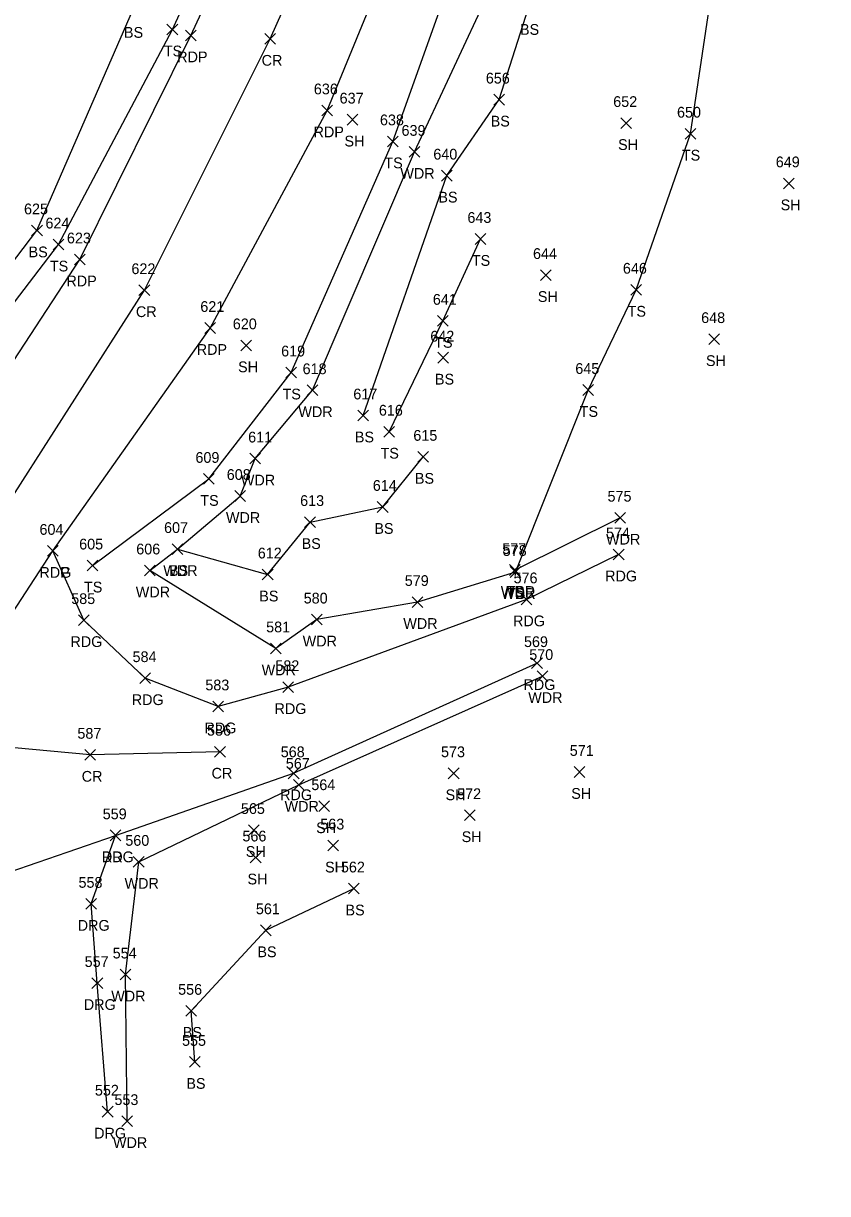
# Model space of a CAD drawing. Extents: x 1586965 to 1590952, y 716317 to 720029.
# Drawn here: x 1587099.1 to 1587248.8, y 719170.5 to 719388.4 of the extents above; entities that cross this region are included whole.
import ezdxf

# ---------------------------------------------------------------- set-up
doc = ezdxf.new("R2010")
doc.units = 0
for name, color, linetype in [('L_A', 7, 'Continuous'), ('L_I', 7, 'Continuous'), ('L_TIC', 7, 'Continuous'), ('LAWA', 7, 'Continuous'), ('LELB', 7, 'Continuous'), ('P_A', 7, 'Continuous'), ('P_I', 7, 'Continuous'), ('P_TIC', 7, 'Continuous'), ('PET', 7, 'Continuous'), ('PEU', 7, 'Continuous'), ('PRC', 7, 'Continuous'), ('R_A', 7, 'Continuous'), ('R_I', 7, 'Continuous'), ('R_TIC', 7, 'Continuous'), ('RDG', 7, 'Continuous')]:
    doc.layers.add(name, color=color, linetype=linetype)

msp = doc.modelspace()

# ---------------------------------------------------------------- linework, layer by layer
at = {"layer": 'L_TIC'}
for points in [[(1587125.81, 719386.29), (1587127.81, 719388.29)], [(1587127.81, 719386.29), (1587125.81, 719388.29)], [(1587186.65, 719373.23), (1587188.65, 719375.23)], [(1587188.65, 719373.23), (1587186.65, 719375.23)], [(1587159.37, 719369.51), (1587161.37, 719371.51)], [(1587161.37, 719369.51), (1587159.37, 719371.51)], [(1587210.32, 719368.87), (1587212.32, 719370.87)], [(1587212.32, 719368.87), (1587210.32, 719370.87)], [(1587222.28, 719366.89), (1587224.28, 719368.89)], [(1587224.28, 719366.89), (1587222.28, 719368.89)], [(1587166.88, 719365.46), (1587168.88, 719367.46)], [(1587168.88, 719365.46), (1587166.88, 719367.46)], [(1587170.91, 719363.5), (1587172.91, 719365.5)], [(1587172.91, 719363.5), (1587170.91, 719365.5)], [(1587176.91, 719359.08), (1587178.91, 719361.08)], [(1587178.91, 719359.08), (1587176.91, 719361.08)], [(1587240.6, 719357.64), (1587242.6, 719359.64)], [(1587242.6, 719357.64), (1587240.6, 719359.64)], [(1587100.6, 719348.88), (1587102.6, 719350.88)], [(1587102.6, 719348.88), (1587100.6, 719350.88)], [(1587183.17, 719347.29), (1587185.17, 719349.29)], [(1587185.17, 719347.29), (1587183.17, 719349.29)], [(1587104.59, 719346.25), (1587106.59, 719348.25)], [(1587106.59, 719346.25), (1587104.59, 719348.25)], [(1587195.38, 719340.57), (1587197.38, 719342.57)], [(1587197.38, 719340.57), (1587195.38, 719342.57)], [(1587212.18, 719337.83), (1587214.18, 719339.83)], [(1587214.18, 719337.83), (1587212.18, 719339.83)], [(1587176.17, 719332.04), (1587178.17, 719334.04)], [(1587178.17, 719332.04), (1587176.17, 719334.04)], [(1587139.56, 719327.48), (1587141.56, 719329.48)], [(1587141.56, 719327.48), (1587139.56, 719329.48)], [(1587226.7, 719328.64), (1587228.7, 719330.64)], [(1587228.7, 719328.64), (1587226.7, 719330.64)], [(1587176.26, 719325.19), (1587178.26, 719327.19)], [(1587178.26, 719325.19), (1587176.26, 719327.19)], [(1587147.92, 719322.42), (1587149.92, 719324.42)], [(1587149.92, 719322.42), (1587147.92, 719324.42)], [(1587151.91, 719319.12), (1587153.91, 719321.12)], [(1587153.91, 719319.12), (1587151.91, 719321.12)], [(1587203.26, 719319.17), (1587205.26, 719321.17)], [(1587205.26, 719319.17), (1587203.26, 719321.17)], [(1587161.35, 719314.42), (1587163.35, 719316.42)], [(1587163.35, 719314.42), (1587161.35, 719316.42)], [(1587166.17, 719311.4), (1587168.17, 719313.4)], [(1587168.17, 719311.4), (1587166.17, 719313.4)], [(1587141.21, 719306.4), (1587143.21, 719308.4)], [(1587143.21, 719306.4), (1587141.21, 719308.4)], [(1587172.54, 719306.72), (1587174.54, 719308.72)], [(1587174.54, 719306.72), (1587172.54, 719308.72)], [(1587132.61, 719302.61), (1587134.61, 719304.61)], [(1587134.61, 719302.61), (1587132.61, 719304.61)], [(1587138.42, 719299.43), (1587140.42, 719301.43)], [(1587140.42, 719299.43), (1587138.42, 719301.43)], [(1587164.98, 719297.39), (1587166.98, 719299.39)], [(1587166.98, 719297.39), (1587164.98, 719299.39)], [(1587151.45, 719294.58), (1587153.45, 719296.58)], [(1587153.45, 719294.58), (1587151.45, 719296.58)], [(1587209.21, 719295.39), (1587211.21, 719297.39)], [(1587211.21, 719295.39), (1587209.21, 719297.39)], [(1587126.75, 719289.55), (1587128.75, 719291.55)], [(1587128.75, 719289.55), (1587126.75, 719291.55)], [(1587126.75, 719289.55), (1587128.75, 719291.55)], [(1587128.75, 719289.55), (1587126.75, 719291.55)], [(1587110.95, 719286.48), (1587112.95, 719288.48)], [(1587112.95, 719286.48), (1587110.95, 719288.48)], [(1587121.63, 719285.56), (1587123.63, 719287.56)], [(1587123.63, 719285.56), (1587121.63, 719287.56)], [(1587143.56, 719284.81), (1587145.56, 719286.81)], [(1587145.56, 719284.81), (1587143.56, 719286.81)], [(1587189.61, 719285.65), (1587191.61, 719287.65)], [(1587191.61, 719285.65), (1587189.61, 719287.65)], [(1587189.61, 719285.65), (1587191.61, 719287.65)], [(1587191.61, 719285.65), (1587189.61, 719287.65)], [(1587189.7, 719285.28), (1587191.7, 719287.28)], [(1587191.7, 719285.28), (1587189.7, 719287.28)], [(1587189.7, 719285.28), (1587191.7, 719287.28)], [(1587191.7, 719285.28), (1587189.7, 719287.28)], [(1587171.46, 719279.69), (1587173.46, 719281.69)], [(1587173.46, 719279.69), (1587171.46, 719281.69)], [(1587152.72, 719276.42), (1587154.72, 719278.42)], [(1587154.72, 719276.42), (1587152.72, 719278.42)], [(1587145.08, 719271.05), (1587147.08, 719273.05)], [(1587147.08, 719271.05), (1587145.08, 719273.05)], [(1587194.72, 719265.91), (1587196.72, 719267.91)], [(1587196.72, 719265.91), (1587194.72, 719267.91)], [(1587178.2, 719247.8), (1587180.2, 719249.8)], [(1587180.2, 719247.8), (1587178.2, 719249.8)], [(1587201.62, 719248.05), (1587203.62, 719250.05)], [(1587203.62, 719248.05), (1587201.62, 719250.05)], [(1587149.35, 719245.65), (1587151.35, 719247.65)], [(1587151.35, 719245.65), (1587149.35, 719247.65)], [(1587154.1, 719241.67), (1587156.1, 719243.67)], [(1587156.1, 719241.67), (1587154.1, 719243.67)], [(1587181.2, 719240), (1587183.2, 719242)], [(1587183.2, 719240), (1587181.2, 719242)], [(1587140.99, 719237.24), (1587142.99, 719239.24)], [(1587142.99, 719237.24), (1587140.99, 719239.24)], [(1587155.76, 719234.34), (1587157.76, 719236.34)], [(1587157.76, 719234.34), (1587155.76, 719236.34)], [(1587119.54, 719231.31), (1587121.54, 719233.31)], [(1587121.54, 719231.31), (1587119.54, 719233.31)], [(1587141.32, 719232.12), (1587143.32, 719234.12)], [(1587143.32, 719232.12), (1587141.32, 719234.12)], [(1587159.61, 719226.35), (1587161.61, 719228.35)], [(1587161.61, 719226.35), (1587159.61, 719228.35)], [(1587143.21, 719218.57), (1587145.21, 719220.57)], [(1587145.21, 719218.57), (1587143.21, 719220.57)], [(1587117.07, 719210.33), (1587119.07, 719212.33)], [(1587119.07, 719210.33), (1587117.07, 719212.33)], [(1587129.31, 719203.57), (1587131.31, 719205.57)], [(1587131.31, 719203.57), (1587129.31, 719205.57)], [(1587129.98, 719194.06), (1587131.98, 719196.06)], [(1587131.98, 719194.06), (1587129.98, 719196.06)], [(1587117.4, 719183.04), (1587119.4, 719185.04)], [(1587119.4, 719183.04), (1587117.4, 719185.04)]]:
    msp.add_lwpolyline(points, dxfattribs=at)
at = {"layer": 'LAWA'}
for points in [[(1587210.21, 719296.39), (1587190.61, 719286.65), (1587190.7, 719286.28), (1587172.46, 719280.69), (1587153.72, 719277.42), (1587146.08, 719272.05), (1587122.63, 719286.56), (1587127.75, 719290.55), (1587139.42, 719300.43), (1587142.21, 719307.4), (1587152.91, 719320.12), (1587171.91, 719364.5), (1587185.92, 719394.62)], [(1587118.4, 719184.04), (1587118.07, 719211.33), (1587120.54, 719232.31), (1587150.35, 719246.65), (1587195.72, 719266.91)]]:
    msp.add_lwpolyline(points, dxfattribs=at)
at = {"layer": 'LELB'}
for points in [[(1586974.22, 719201.38), (1587004.64, 719224.97), (1587038.23, 719264.63), (1587070.35, 719308.83), (1587101.6, 719349.88), (1587119.36, 719390.75), (1587135.94, 719419.64), (1587149.18, 719457.32), (1587161.88, 719497.01), (1587171.82, 719537.32), (1587183.93, 719559.95), (1587196.31, 719595.67), (1587210.79, 719616.33), (1587226.54, 719644.19), (1587252.78, 719668.03), (1587275.41, 719699.75), (1587291.25, 719715.32), (1587307.92, 719729.13), (1587319.25, 719735.05), (1587320, 719753.34), (1587323.07, 719768.88), (1587320.57, 719781.92), (1587330.74, 719804.48), (1587340.87, 719823.38)], [(1586974.22, 719201.38), (1587004.64, 719224.97), (1587038.23, 719264.63), (1587070.35, 719308.83), (1587101.6, 719349.88), (1587119.36, 719390.75), (1587135.94, 719419.64), (1587149.18, 719457.32), (1587161.88, 719497.01), (1587171.82, 719537.32), (1587183.93, 719559.95), (1587196.31, 719595.67), (1587210.79, 719616.33), (1587226.54, 719644.19), (1587252.78, 719668.03), (1587275.41, 719699.75), (1587291.25, 719715.32), (1587307.92, 719729.13), (1587319.25, 719735.05), (1587320, 719753.34), (1587323.07, 719768.88), (1587320.57, 719781.92), (1587330.74, 719804.48), (1587340.87, 719823.38)], [(1586978.66, 719194.77), (1587009.14, 719220.21), (1587042.41, 719260.62), (1587074.55, 719306.69), (1587105.59, 719347.25), (1587126.81, 719387.29), (1587140.39, 719417.03), (1587155.04, 719455.09), (1587167.34, 719494.49), (1587179.82, 719533.81), (1587190.9, 719559.88), (1587204.29, 719592.61), (1587216.76, 719611.7), (1587236.63, 719636.62), (1587258.85, 719661.96), (1587283.81, 719691.81), (1587311.82, 719715.76), (1587323.53, 719725.34), (1587349.89, 719742.95), (1587377.37, 719757.84), (1587414.05, 719779.22)], [(1586978.66, 719194.77), (1587009.14, 719220.21), (1587042.41, 719260.62), (1587074.55, 719306.69), (1587105.59, 719347.25), (1587126.81, 719387.29), (1587140.39, 719417.03), (1587155.04, 719455.09), (1587167.34, 719494.49), (1587179.82, 719533.81), (1587190.9, 719559.88), (1587204.29, 719592.61), (1587216.76, 719611.7), (1587236.63, 719636.62), (1587258.85, 719661.96), (1587283.81, 719691.81), (1587311.82, 719715.76), (1587323.53, 719725.34), (1587349.89, 719742.95), (1587377.37, 719757.84), (1587414.05, 719779.22)], [(1587111.95, 719287.48), (1587133.61, 719303.61), (1587148.92, 719323.42), (1587167.88, 719366.46), (1587179.01, 719397.6), (1587173.15, 719399.12), (1587186.97, 719441.05), (1587200.36, 719482.43), (1587215.71, 719524.53), (1587222.82, 719545.46), (1587239.38, 719574.3), (1587247.92, 719589.42), (1587267.49, 719614.08), (1587286.95, 719636.16), (1587313.61, 719660.46), (1587335.34, 719679.69), (1587361.68, 719697.91), (1587398.24, 719722.21), (1587438.94, 719742.74)], [(1587111.95, 719287.48), (1587133.61, 719303.61), (1587148.92, 719323.42), (1587167.88, 719366.46), (1587179.01, 719397.6), (1587173.15, 719399.12), (1587186.97, 719441.05), (1587200.36, 719482.43), (1587215.71, 719524.53), (1587222.82, 719545.46), (1587239.38, 719574.3), (1587247.92, 719589.42), (1587267.49, 719614.08), (1587286.95, 719636.16), (1587313.61, 719660.46), (1587335.34, 719679.69), (1587361.68, 719697.91), (1587398.24, 719722.21), (1587438.94, 719742.74)], [(1587190.7, 719286.28), (1587204.26, 719320.17), (1587213.18, 719338.83), (1587223.28, 719367.89), (1587232.07, 719426.53), (1587236.03, 719457.93), (1587241.48, 719477.28), (1587241.71, 719512.51), (1587244.4, 719534.33), (1587244.22, 719544.51)], [(1587190.7, 719286.28), (1587204.26, 719320.17), (1587213.18, 719338.83), (1587223.28, 719367.89), (1587232.07, 719426.53), (1587236.03, 719457.93), (1587241.48, 719477.28), (1587241.71, 719512.51), (1587244.4, 719534.33), (1587244.22, 719544.51)], [(1587162.35, 719315.42), (1587177.91, 719360.08), (1587187.65, 719374.23), (1587193.11, 719391.3), (1587194.51, 719437.33)], [(1587162.35, 719315.42), (1587177.91, 719360.08), (1587187.65, 719374.23), (1587193.11, 719391.3), (1587194.51, 719437.33)], [(1587167.17, 719312.4), (1587177.17, 719333.04), (1587184.17, 719348.29)], [(1587167.17, 719312.4), (1587177.17, 719333.04), (1587184.17, 719348.29)], [(1587127.75, 719290.55), (1587144.56, 719285.81), (1587152.45, 719295.58), (1587165.98, 719298.39), (1587173.54, 719307.72)], [(1587127.75, 719290.55), (1587144.56, 719285.81), (1587152.45, 719295.58), (1587165.98, 719298.39), (1587173.54, 719307.72)], [(1587130.98, 719195.06), (1587130.31, 719204.57), (1587144.21, 719219.57), (1587160.61, 719227.35)], [(1587130.98, 719195.06), (1587130.31, 719204.57), (1587144.21, 719219.57), (1587160.61, 719227.35)]]:
    msp.add_lwpolyline(points, dxfattribs=at)
at = {"layer": 'P_TIC'}
for points in [[(1587129.23, 719385.19), (1587131.23, 719387.19)], [(1587131.23, 719385.19), (1587129.23, 719387.19)], [(1587144.01, 719384.55), (1587146.01, 719386.55)], [(1587146.01, 719384.55), (1587144.01, 719386.55)], [(1587154.62, 719371.22), (1587156.62, 719373.22)], [(1587156.62, 719371.22), (1587154.62, 719373.22)], [(1587108.59, 719343.47), (1587110.59, 719345.47)], [(1587110.59, 719343.47), (1587108.59, 719345.47)], [(1587120.6, 719337.75), (1587122.6, 719339.75)], [(1587122.6, 719337.75), (1587120.6, 719339.75)], [(1587132.86, 719330.71), (1587134.86, 719332.71)], [(1587134.86, 719330.71), (1587132.86, 719332.71)], [(1587103.56, 719289.21), (1587105.56, 719291.21)], [(1587105.56, 719289.21), (1587103.56, 719291.21)], [(1587103.56, 719289.21), (1587105.56, 719291.21)], [(1587105.56, 719289.21), (1587103.56, 719291.21)], [(1587208.92, 719288.54), (1587210.92, 719290.54)], [(1587210.92, 719288.54), (1587208.92, 719290.54)], [(1587191.76, 719280.18), (1587193.76, 719282.18)], [(1587193.76, 719280.18), (1587191.76, 719282.18)], [(1587109.34, 719276.32), (1587111.34, 719278.32)], [(1587111.34, 719276.32), (1587109.34, 719278.32)], [(1587193.71, 719268.31), (1587195.71, 719270.31)], [(1587195.71, 719268.31), (1587193.71, 719270.31)], [(1587120.76, 719265.51), (1587122.76, 719267.51)], [(1587122.76, 719265.51), (1587120.76, 719267.51)], [(1587147.36, 719263.84), (1587149.36, 719265.84)], [(1587149.36, 719263.84), (1587147.36, 719265.84)], [(1587134.32, 719260.25), (1587136.32, 719262.25)], [(1587136.32, 719260.25), (1587134.32, 719262.25)], [(1587110.5, 719251.24), (1587112.5, 719253.24)], [(1587112.5, 719251.24), (1587110.5, 719253.24)], [(1587134.69, 719251.82), (1587136.69, 719253.82)], [(1587136.69, 719251.82), (1587134.69, 719253.82)], [(1587148.4, 719247.8), (1587150.4, 719249.8)], [(1587150.4, 719247.8), (1587148.4, 719249.8)], [(1587115.21, 719236.25), (1587117.21, 719238.25)], [(1587117.21, 719236.25), (1587115.21, 719238.25)]]:
    msp.add_lwpolyline(points, dxfattribs=at)
at = {"layer": 'PET'}
for points in [[(1586981.32, 719191.44), (1587010.72, 719218.17), (1587046.97, 719256.26), (1587081.9, 719302.22), (1587109.59, 719344.47), (1587130.23, 719386.19), (1587143.83, 719415.56), (1587158.67, 719453.12), (1587172.27, 719492.43), (1587186.37, 719531.4), (1587196.72, 719557.08), (1587212.09, 719588.4), (1587223.39, 719607.14), (1587242.2, 719632.56), (1587263.71, 719657.85), (1587289.89, 719684.48), (1587313.81, 719705.37), (1587345, 719730.07), (1587380.68, 719751.95), (1587418.28, 719771.56)], [(1586998.3, 719170.55), (1587031.46, 719201.5), (1587048.24, 719215.72), (1587069.37, 719240.81), (1587083.56, 719258.07), (1587104.56, 719290.21), (1587133.86, 719331.71), (1587155.62, 719372.22), (1587169, 719404.76), (1587183.27, 719443.5), (1587197.56, 719483.83), (1587211.74, 719526.3), (1587221.19, 719546.28), (1587236.84, 719576.04), (1587246.13, 719590.54), (1587264.51, 719616.23), (1587283.97, 719638.96), (1587310.1, 719664.5), (1587332.49, 719682.99), (1587358.98, 719703.31), (1587395.82, 719726.18), (1587435.88, 719747.89)]]:
    msp.add_lwpolyline(points, dxfattribs=at)
at = {"layer": 'PEU'}
for points in [[(1587209.92, 719289.54), (1587192.76, 719281.18), (1587148.36, 719264.84), (1587135.32, 719261.25), (1587121.76, 719266.51), (1587110.34, 719277.32), (1587104.56, 719290.21)], [(1587048.24, 719215.72), (1587058.65, 719217.57), (1587078.39, 719224.18), (1587116.21, 719237.25), (1587149.4, 719248.8), (1587194.71, 719269.31)]]:
    msp.add_lwpolyline(points, dxfattribs=at)
at = {"layer": 'PRC'}
for points in [[(1586989.8, 719181.42), (1587021.35, 719209.83), (1587057.54, 719247.82), (1587093.64, 719295.06), (1587121.6, 719338.75), (1587145.01, 719385.55), (1587156.05, 719410.32), (1587170.73, 719448.3), (1587185.3, 719487.87), (1587199.88, 719528.69), (1587209.21, 719551.28), (1587224.26, 719582.11), (1587235.22, 719599.27), (1587253.6, 719624.57), (1587274.17, 719648.49), (1587299.95, 719674.27), (1587323.51, 719694.22), (1587352.02, 719715.49), (1587388.91, 719738.13), (1587428.57, 719759.37)], [(1586989.8, 719181.42), (1587021.35, 719209.83), (1587057.54, 719247.82), (1587093.64, 719295.06), (1587121.6, 719338.75), (1587145.01, 719385.55), (1587156.05, 719410.32), (1587170.73, 719448.3), (1587185.3, 719487.87), (1587199.88, 719528.69), (1587209.21, 719551.28), (1587224.26, 719582.11), (1587235.22, 719599.27), (1587253.6, 719624.57), (1587274.17, 719648.49), (1587299.95, 719674.27), (1587323.51, 719694.22), (1587352.02, 719715.49), (1587388.91, 719738.13), (1587428.57, 719759.37)], [(1587135.69, 719252.82), (1587111.5, 719252.24), (1587093.33, 719253.91), (1587083.56, 719258.07)], [(1587135.69, 719252.82), (1587111.5, 719252.24), (1587093.33, 719253.91), (1587083.56, 719258.07)]]:
    msp.add_lwpolyline(points, dxfattribs=at)
at = {"layer": 'R_TIC'}
for points in [[(1587115.21, 719236.25), (1587117.21, 719238.25)], [(1587117.21, 719236.25), (1587115.21, 719238.25)], [(1587110.7, 719223.49), (1587112.7, 719225.49)], [(1587112.7, 719223.49), (1587110.7, 719225.49)], [(1587111.84, 719208.75), (1587113.84, 719210.75)], [(1587113.84, 719208.75), (1587111.84, 719210.75)], [(1587113.76, 719184.8), (1587115.76, 719186.8)], [(1587115.76, 719184.8), (1587113.76, 719186.8)]]:
    msp.add_lwpolyline(points, dxfattribs=at)
at = {"layer": 'RDG'}
msp.add_lwpolyline([(1587114.76, 719185.8), (1587112.84, 719209.75), (1587111.7, 719224.49), (1587116.21, 719237.25)], dxfattribs=at)

# ---------------------------------------------------------------- texts
at = {"layer": 'L_A'}
for s, p in [('BS', (1587191.55, 719386.3)), ('BS', (1587117.8, 719385.75)), ('TS', (1587125.22, 719382.29)), ('BS', (1587186.09, 719369.23)), ('SH', (1587158.86, 719365.51)), ('SH', (1587209.81, 719364.87)), ('TS', (1587221.69, 719362.89)), ('TS', (1587166.29, 719361.46)), ('WDR', (1587169.27, 719359.5)), ('BS', (1587176.35, 719355.08)), ('SH', (1587240.09, 719353.64)), ('BS', (1587100.04, 719344.88)), ('TS', (1587182.58, 719343.29)), ('TS', (1587104, 719342.25)), ('SH', (1587194.87, 719336.57)), ('TS', (1587211.59, 719333.83)), ('TS', (1587175.58, 719328.04)), ('SH', (1587139.05, 719323.48)), ('SH', (1587226.18, 719324.64)), ('BS', (1587175.71, 719321.19)), ('TS', (1587147.33, 719318.42)), ('WDR', (1587150.28, 719315.12)), ('TS', (1587202.67, 719315.17)), ('BS', (1587160.8, 719310.42)), ('TS', (1587165.58, 719307.4)), ('WDR', (1587139.57, 719302.4)), ('BS', (1587171.98, 719302.72)), ('TS', (1587132.02, 719298.61)), ('WDR', (1587136.79, 719295.43)), ('BS', (1587164.43, 719293.39)), ('BS', (1587150.89, 719290.58)), ('WDR', (1587207.57, 719291.39)), ('WDR', (1587125.12, 719285.55)), ('BS', (1587126.19, 719285.55)), ('TS', (1587110.36, 719282.48)), ('WDR', (1587120, 719281.56)), ('WDR', (1587187.97, 719281.65)), ('TS', (1587189.02, 719281.65)), ('BS', (1587143, 719280.81)), ('WDR', (1587188.06, 719281.28)), ('TS', (1587189.11, 719281.28)), ('WDR', (1587169.82, 719275.69)), ('WDR', (1587151.08, 719272.42)), ('WDR', (1587143.44, 719267.05)), ('WDR', (1587193.08, 719261.91)), ('SH', (1587177.69, 719243.8)), ('SH', (1587201.1, 719244.05)), ('WDR', (1587147.71, 719241.65)), ('SH', (1587153.59, 719237.67)), ('SH', (1587180.69, 719236)), ('SH', (1587140.48, 719233.24)), ('SH', (1587155.25, 719230.34)), ('WDR', (1587117.91, 719227.31)), ('SH', (1587140.81, 719228.12)), ('BS', (1587159.05, 719222.35)), ('BS', (1587142.65, 719214.57)), ('WDR', (1587115.43, 719206.33)), ('BS', (1587128.75, 719199.57)), ('BS', (1587129.42, 719190.06)), ('WDR', (1587115.76, 719179.04))]:
    msp.add_text(s, height=2, dxfattribs=at).set_placement(p)
at = {"layer": 'L_I'}
for s, p in [('656', (1587185.19, 719377.23)), ('637', (1587157.96, 719373.51)), ('652', (1587208.91, 719372.87)), ('650', (1587220.79, 719370.89)), ('638', (1587165.47, 719369.46)), ('639', (1587169.49, 719367.5)), ('640', (1587175.41, 719363.08)), ('649', (1587239.18, 719361.64)), ('625', (1587099.19, 719352.88)), ('643', (1587181.76, 719351.29)), ('624', (1587103.18, 719350.25)), ('644', (1587193.97, 719344.57)), ('646', (1587210.71, 719341.83)), ('641', (1587175.32, 719336.04)), ('620', (1587138.07, 719331.48)), ('648', (1587225.29, 719332.64)), ('642', (1587174.85, 719329.19)), ('619', (1587147.07, 719326.42)), ('618', (1587151.07, 719323.12)), ('645', (1587201.85, 719323.17)), ('617', (1587160.51, 719318.42)), ('616', (1587165.27, 719315.4)), ('611', (1587140.93, 719310.4)), ('615', (1587171.69, 719310.72)), ('609', (1587131.11, 719306.61)), ('608', (1587136.94, 719303.43)), ('614', (1587164.14, 719301.39)), ('575', (1587207.85, 719299.39)), ('613', (1587150.61, 719298.58)), ('607', (1587125.27, 719293.55)), ('607', (1587125.27, 719293.55)), ('605', (1587109.46, 719290.48)), ('606', (1587120.09, 719289.56)), ('612', (1587142.72, 719288.81)), ('577', (1587188.24, 719289.65)), ('577', (1587188.24, 719289.65)), ('578', (1587188.33, 719289.28)), ('578', (1587188.33, 719289.28)), ('579', (1587170.09, 719283.69)), ('580', (1587151.27, 719280.42)), ('581', (1587144.28, 719275.05)), ('570', (1587193.27, 719269.91)), ('573', (1587176.84, 719251.8)), ('571', (1587200.82, 719252.05)), ('567', (1587147.94, 719249.65)), ('564', (1587152.69, 719245.67)), ('572', (1587179.84, 719244)), ('565', (1587139.58, 719241.24)), ('563', (1587154.36, 719238.34)), ('566', (1587139.86, 719236.12)), ('560', (1587118.05, 719235.31)), ('562', (1587158.2, 719230.35)), ('561', (1587142.37, 719222.57)), ('554', (1587115.7, 719214.33)), ('556', (1587127.89, 719207.57)), ('555', (1587128.61, 719198.06)), ('553', (1587116.03, 719187.04))]:
    msp.add_text(s, height=2, dxfattribs=at).set_placement(p)
at = {"layer": 'P_A'}
for s, p in [('RDP', (1587127.72, 719381.19)), ('CR', (1587143.44, 719380.55)), ('RDP', (1587153.11, 719367.22)), ('RDP', (1587107.08, 719339.47)), ('CR', (1587120.03, 719333.75)), ('RDP', (1587131.35, 719326.71)), ('RDG', (1587102.05, 719285.21)), ('RDP', (1587102.05, 719285.21)), ('RDG', (1587207.41, 719284.54)), ('RDG', (1587190.25, 719276.18)), ('RDG', (1587107.83, 719272.32)), ('RDG', (1587192.2, 719264.31)), ('RDG', (1587119.25, 719261.51)), ('RDG', (1587145.84, 719259.84)), ('RDG', (1587132.8, 719256.25)), ('CR', (1587109.93, 719247.24)), ('CR', (1587134.12, 719247.82)), ('RDG', (1587146.88, 719243.8)), ('RDG', (1587113.69, 719232.25))]:
    msp.add_text(s, height=2, dxfattribs=at).set_placement(p)
at = {"layer": 'P_I'}
for s, p in [('636', (1587153.16, 719375.22)), ('623', (1587107.18, 719347.47)), ('622', (1587119.19, 719341.75)), ('621', (1587132.02, 719334.71)), ('604', (1587102.07, 719293.21)), ('604', (1587102.07, 719293.21)), ('574', (1587207.56, 719292.54)), ('576', (1587190.35, 719284.18)), ('585', (1587107.98, 719280.32)), ('569', (1587192.29, 719272.31)), ('584', (1587119.4, 719269.51)), ('582', (1587145.99, 719267.84)), ('583', (1587132.95, 719264.25)), ('587', (1587109.13, 719255.24)), ('586', (1587133.27, 719255.82)), ('568', (1587146.99, 719251.8)), ('559', (1587113.84, 719240.25))]:
    msp.add_text(s, height=2, dxfattribs=at).set_placement(p)
at = {"layer": 'R_A'}
for p in [(1587113.69, 719232.25), (1587109.19, 719219.49), (1587110.33, 719204.75), (1587112.25, 719180.8)]:
    msp.add_text('DRG', height=2, dxfattribs=at).set_placement(p)
at = {"layer": 'R_I'}
for s, p in [('559', (1587113.84, 719240.25)), ('558', (1587109.34, 719227.49)), ('557', (1587110.48, 719212.75)), ('552', (1587112.39, 719188.8))]:
    msp.add_text(s, height=2, dxfattribs=at).set_placement(p)

doc.saveas('drawing.dxf')
